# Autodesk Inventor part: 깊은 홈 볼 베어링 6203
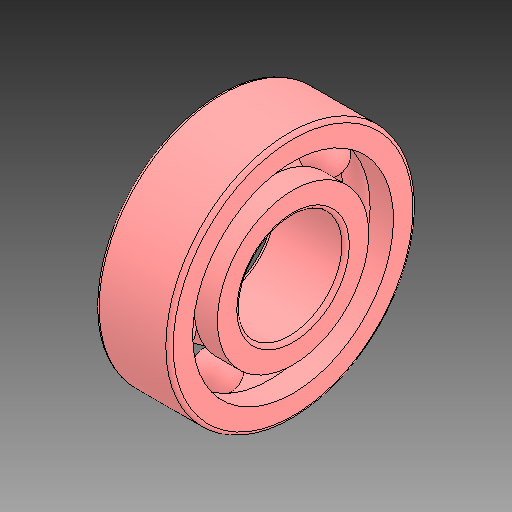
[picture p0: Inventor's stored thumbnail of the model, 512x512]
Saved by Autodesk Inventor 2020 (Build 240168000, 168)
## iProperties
Created: 2025-03
Part Number: 깊은 홈 볼 베어링 6203
Material: 강철, 연강
Description: 깊은 그루브 볼 베어링
Document SubType Name: Modeling
Designer: CA01
Density: 7.85 g/cm^3
Appearance: 기본값
Author: jhkim
Sending System: Autodesk Inventor 2025
Preprocessor: ST-DEVELOPER v20
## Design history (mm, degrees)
feature "Solid1"
feature "Solid1:1"
feature "Solid1:2"
feature "Solid1:3"
feature "Solid1:4"
feature "Solid1:5"
feature "Solid1:6"
feature "Solid1:7"
feature "Solid1:8"
node "솔리드1"
node "솔리드2"
node "솔리드3"
node "솔리드4"
node "솔리드5"
node "솔리드6"
node "솔리드7"
node "솔리드8"
node "솔리드9"
